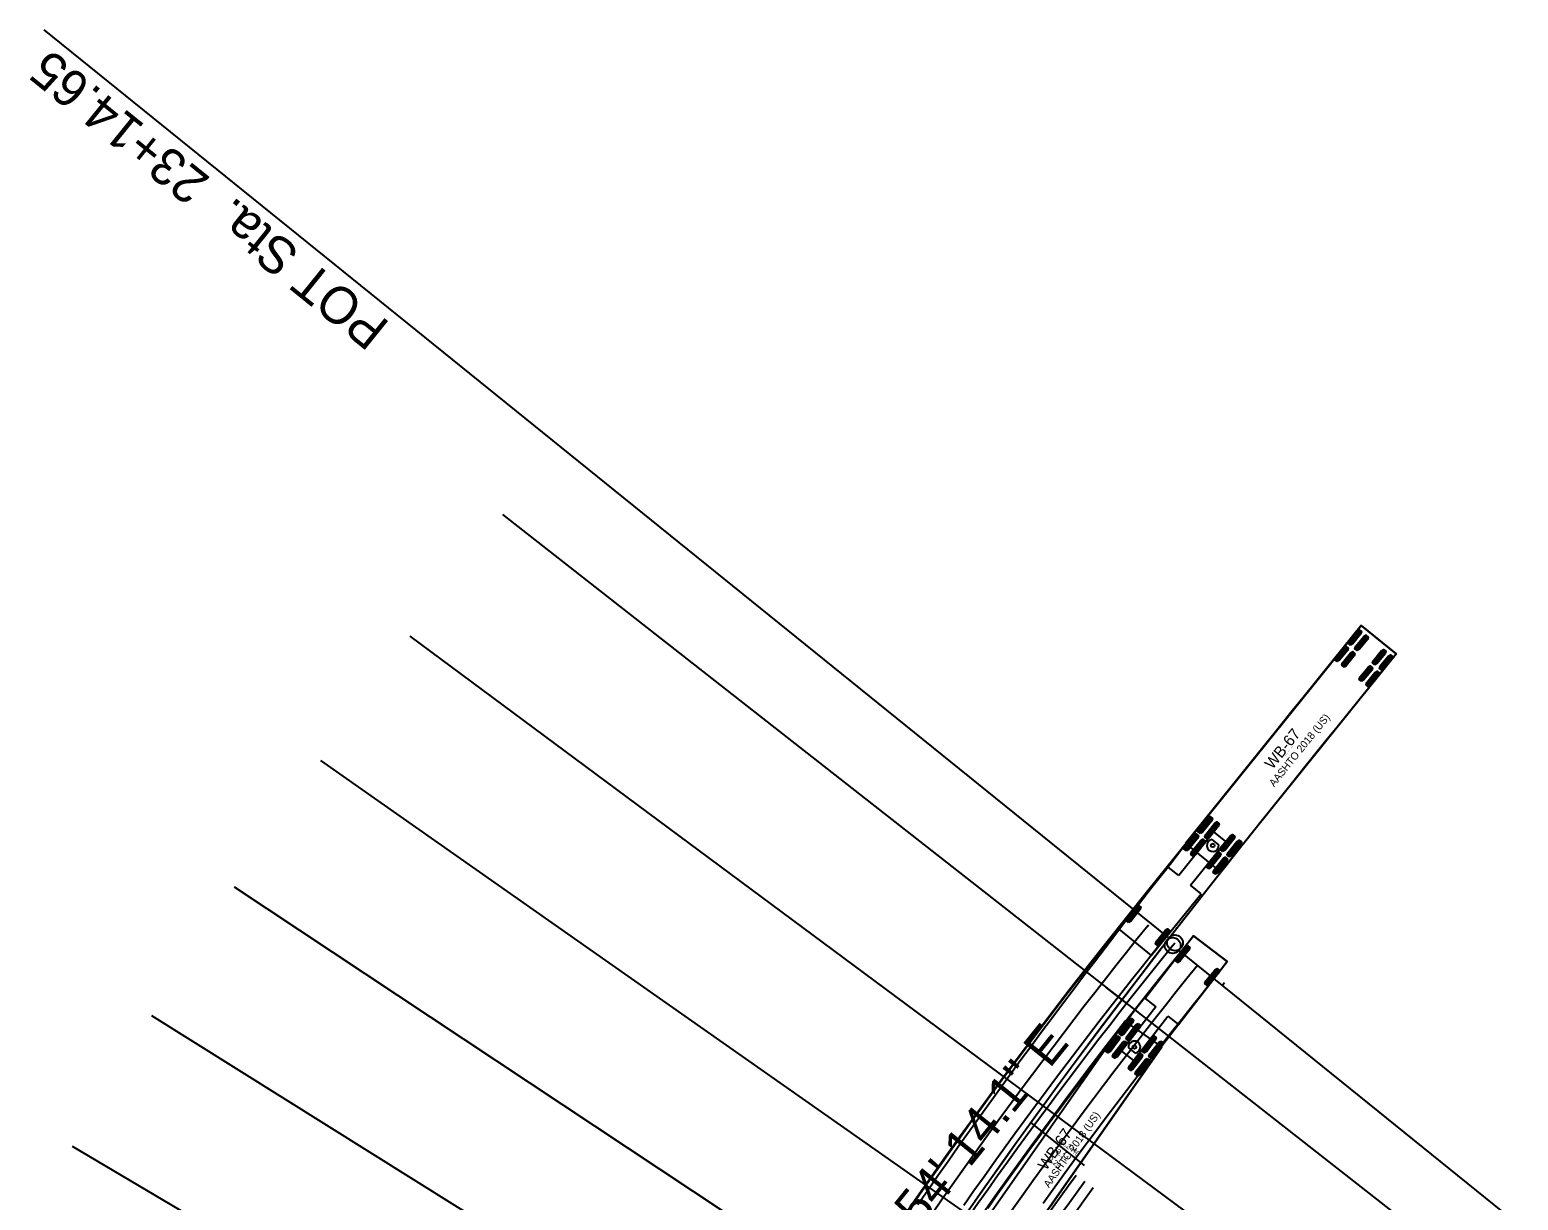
# Model space of a CAD drawing. Extents: x 2293233 to 2294507, y 892788 to 894229.
# Drawn here: x 2294076 to 2294357.6, y 894007.4 to 894228.8 of the extents above; entities that cross this region are included whole.
import ezdxf

# ---------------------------------------------------------------- set-up
doc = ezdxf.new("R2010")
doc.units = 0
for name, color, linetype in [('COGO Default Curve', 7, 'Continuous'), ('Default', 7, 'Continuous'), ('Prop EOT', 7, 'Continuous'), ('Prop Horizontal Alignment', 7, 'Continuous'), ('Prop Paved Shoulder', 7, 'Continuous'), ('Scratch_Level_4', 7, 'Continuous'), ('Scratch_Level_5', 7, 'Continuous'), ('Scratch_Level_6', 7, 'Continuous')]:
    doc.layers.add(name, color=color, linetype=linetype)

msp = doc.modelspace()

# ---------------------------------------------------------------- linework, layer by layer
at = {"layer": 'COGO Default Curve'}
for p, q in [((2294327.95, 894116.1), (2294294.66, 894074.86)), ((2294334.56, 894110.76), (2294327.95, 894116.1)), ((2294325.52, 894112.73), (2294327.59, 894115.3)), ((2294325.7, 894112.58), (2294327.77, 894115.15)), ((2294325.87, 894112.44), (2294327.95, 894115.01)), ((2294326.8, 894111.69), (2294328.87, 894114.26)), ((2294326.98, 894111.55), (2294329.05, 894114.11)), ((2294327.16, 894111.4), (2294329.23, 894113.97)), ((2294301.28, 894069.52), (2294334.56, 894110.76)), ((2294323.01, 894109.61), (2294325.08, 894112.18)), ((2294323.18, 894109.47), (2294325.26, 894112.04)), ((2294323.36, 894109.33), (2294325.43, 894111.89)), ((2294324.29, 894108.58), (2294326.36, 894111.15)), ((2294324.47, 894108.43), (2294326.54, 894111)), ((2294324.65, 894108.29), (2294326.72, 894110.86)), ((2294330.13, 894109), (2294332.21, 894111.57)), ((2294330.31, 894108.86), (2294332.39, 894111.42)), ((2294330.49, 894108.71), (2294332.56, 894111.28)), ((2294331.42, 894107.96), (2294333.49, 894110.53)), ((2294331.6, 894107.82), (2294333.67, 894110.39)), ((2294331.78, 894107.68), (2294333.85, 894110.24)), ((2294327.62, 894105.89), (2294329.7, 894108.46)), ((2294327.8, 894105.74), (2294329.87, 894108.31)), ((2294327.98, 894105.6), (2294330.05, 894108.17)), ((2294328.91, 894104.85), (2294330.98, 894107.42)), ((2294329.08, 894104.71), (2294331.16, 894107.28)), ((2294329.26, 894104.56), (2294331.34, 894107.13)), ((2294297.08, 894077.1), (2294299.39, 894079.95)), ((2294297.26, 894076.95), (2294299.57, 894079.81)), ((2294297.44, 894076.81), (2294299.74, 894079.66)), ((2294300.06, 894077.06), (2294293.4, 894068.81)), ((2294294.45, 894073.83), (2294296.75, 894076.68)), ((2294294.63, 894073.68), (2294296.93, 894076.54)), ((2294298.37, 894076.06), (2294300.67, 894078.91)), ((2294298.55, 894075.92), (2294300.85, 894078.77)), ((2294298.73, 894075.77), (2294301.03, 894078.63)), ((2294302.29, 894075.26), (2294300.06, 894077.06)), ((2294301.31, 894073.68), (2294303.62, 894076.54)), ((2294294.66, 894074.86), (2294301.28, 894069.52)), ((2294294.8, 894073.54), (2294297.11, 894076.39)), ((2294295.63, 894067.01), (2294302.29, 894075.26)), ((2294295.73, 894072.79), (2294298.03, 894075.65)), ((2294295.91, 894072.65), (2294298.21, 894075.5)), ((2294296.09, 894072.5), (2294298.39, 894075.36)), ((2294300.99, 894074.64), (2294299.73, 894075.66)), ((2294301.49, 894073.54), (2294303.79, 894076.39)), ((2294301.67, 894073.4), (2294303.97, 894076.25)), ((2294302.6, 894072.65), (2294304.9, 894075.5)), ((2294302.78, 894072.5), (2294305.08, 894075.36)), ((2294302.95, 894072.36), (2294305.26, 894075.21)), ((2294298.68, 894070.42), (2294300.98, 894073.27)), ((2294298.85, 894070.27), (2294301.16, 894073.13)), ((2294299.03, 894070.13), (2294301.33, 894072.98)), ((2294299.96, 894069.38), (2294302.26, 894072.23)), ((2294300.14, 894069.24), (2294302.44, 894072.09)), ((2294300.32, 894069.09), (2294302.62, 894071.95)), ((2294291.4, 894070.42), (2294281.98, 894058.75)), ((2294293.4, 894068.81), (2294291.4, 894070.42)), ((2294301.28, 894069.52), (2294301.28, 894069.52)), ((2294288.21, 894053.72), (2294297.63, 894065.39)), ((2294297.63, 894065.39), (2294295.63, 894067.01)), ((2294283.52, 894060.29), (2294285.82, 894063.14)), ((2294283.7, 894060.14), (2294286, 894063)), ((2294283.88, 894060), (2294286.18, 894062.85)), ((2294281.98, 894058.75), (2294288.21, 894053.72)), ((2294296.23, 894057.42), (2294287.05, 894045.55)), ((2294289.03, 894055.84), (2294291.33, 894058.69)), ((2294289.21, 894055.7), (2294291.51, 894058.55)), ((2294289.39, 894055.55), (2294291.69, 894058.41)), ((2294302.55, 894052.53), (2294296.23, 894057.42)), ((2294296.23, 894057.42), (2294296.23, 894057.42)), ((2294295.12, 894055.55), (2294292.82, 894052.7)), ((2294295.3, 894055.41), (2294293, 894052.56)), ((2294295.48, 894055.27), (2294293.17, 894052.41)), ((2294288.21, 894053.72), (2294288.21, 894053.72)), ((2294293.38, 894040.66), (2294302.55, 894052.53)), ((2294300.71, 894051.21), (2294298.41, 894048.35)), ((2294300.89, 894051.06), (2294298.59, 894048.21)), ((2294301.07, 894050.92), (2294298.77, 894048.07)), ((2294287.05, 894045.55), (2294289.08, 894043.98)), ((2294289.08, 894043.98), (2294282.6, 894035.6)), ((2294283.26, 894041.28), (2294252.82, 893997.89)), ((2294284.44, 894041.8), (2294282.2, 894038.9)), ((2294284.62, 894041.66), (2294282.38, 894038.76)), ((2294284.8, 894041.52), (2294282.56, 894038.62)), ((2294290.22, 894036.4), (2294283.26, 894041.28)), ((2294283.26, 894041.28), (2294283.26, 894041.28)), ((2294285.74, 894040.79), (2294283.5, 894037.89)), ((2294285.93, 894040.65), (2294283.68, 894037.75)), ((2294286.11, 894040.51), (2294283.86, 894037.61)), ((2294284.87, 894033.85), (2294291.35, 894042.23)), ((2294291.35, 894042.23), (2294293.38, 894040.66)), ((2294281.87, 894038.48), (2294279.63, 894035.58)), ((2294282.05, 894038.34), (2294279.81, 894035.44)), ((2294282.23, 894038.2), (2294279.99, 894035.3)), ((2294283.18, 894037.47), (2294280.93, 894034.57)), ((2294283.36, 894037.33), (2294281.11, 894034.43)), ((2294283.54, 894037.19), (2294281.3, 894034.29)), ((2294288.74, 894038.48), (2294286.49, 894035.58)), ((2294288.92, 894038.34), (2294286.68, 894035.44)), ((2294289.1, 894038.2), (2294286.86, 894035.3)), ((2294290.04, 894037.47), (2294287.8, 894034.57)), ((2294290.22, 894037.33), (2294287.98, 894034.43)), ((2294290.41, 894037.19), (2294288.16, 894034.29)), ((2294259.78, 893993.01), (2294290.22, 894036.4)), ((2294282.6, 894035.6), (2294284.87, 894033.85)), ((2294283.88, 894036.24), (2294285.16, 894035.25)), ((2294286.17, 894035.16), (2294283.93, 894032.25)), ((2294286.35, 894035.02), (2294284.11, 894032.11)), ((2294286.53, 894034.88), (2294284.29, 894031.97)), ((2294287.47, 894034.15), (2294285.23, 894031.25)), ((2294287.66, 894034.01), (2294285.41, 894031.11)), ((2294287.84, 894033.87), (2294285.59, 894030.97))]:
    msp.add_line(p, q, dxfattribs=at)
for points in [[(2294240.06, 894002.5), (2294243.86, 894007.98), (2294247.88, 894013.71), (2294251.95, 894019.4), (2294256.06, 894025.07), (2294260.2, 894030.7), (2294264.39, 894036.31), (2294268.62, 894041.89), (2294272.88, 894047.43), (2294279.86, 894056.36), (2294287.54, 894066.01), (2294327.09, 894115.04), (2294327.76, 894115.84), (2294327.95, 894116.1), (2294334.56, 894110.76), (2294333.71, 894109.7)], [(2294325.12, 894112.6), (2294323.03, 894110), (2294320.93, 894107.41), (2294318.84, 894104.82), (2294316.75, 894102.22), (2294314.65, 894099.63), (2294312.56, 894097.03), (2294310.47, 894094.43), (2294308.38, 894091.83), (2294306.29, 894089.23), (2294304.21, 894086.62), (2294302.13, 894084.02), (2294300.05, 894081.41), (2294297.97, 894078.8), (2294295.89, 894076.18), (2294293.82, 894073.56), (2294291.76, 894070.94), (2294289.7, 894068.31), (2294287.64, 894065.68), (2294285.59, 894063.05), (2294283.54, 894060.41), (2294281.5, 894057.76), (2294279.47, 894055.11), (2294277.44, 894052.46), (2294275.41, 894049.8), (2294273.4, 894047.14), (2294271.39, 894044.47), (2294269.39, 894041.79), (2294267.39, 894039.11), (2294265.4, 894036.43), (2294263.42, 894033.74), (2294261.45, 894031.04), (2294259.48, 894028.34), (2294257.52, 894025.63), (2294255.57, 894022.91), (2294253.63, 894020.19), (2294251.7, 894017.47), (2294249.77, 894014.74), (2294247.85, 894012), (2294245.94, 894009.25), (2294244.04, 894006.5)], [(2294333.71, 894109.7), (2294313.42, 894084.53), (2294306.55, 894075.93), (2294300.54, 894068.36), (2294294.37, 894060.49), (2294288.65, 894053.11), (2294283.18, 894045.97), (2294277.95, 894039.05), (2294272.38, 894031.56), (2294267.06, 894024.3), (2294261.79, 894017), (2294256.78, 894009.93), (2294251.82, 894002.81)], [(2294331.73, 894107.26), (2294329.64, 894104.67), (2294327.55, 894102.07), (2294325.46, 894099.48), (2294323.36, 894096.89), (2294321.27, 894094.29), (2294319.18, 894091.7), (2294317.1, 894089.1), (2294315.01, 894086.51), (2294312.93, 894083.91), (2294310.85, 894081.31), (2294308.77, 894078.71), (2294306.69, 894076.11), (2294304.62, 894073.51), (2294302.56, 894070.9), (2294300.5, 894068.3), (2294298.44, 894065.68), (2294296.39, 894063.07), (2294294.34, 894060.45), (2294292.3, 894057.83), (2294290.26, 894055.21), (2294288.23, 894052.58), (2294286.21, 894049.94), (2294284.19, 894047.3), (2294282.18, 894044.66), (2294280.18, 894042.02), (2294278.18, 894039.36), (2294276.2, 894036.71), (2294274.21, 894034.04), (2294272.24, 894031.38), (2294270.27, 894028.71), (2294268.31, 894026.03), (2294266.36, 894023.35), (2294264.42, 894020.66), (2294262.48, 894017.96), (2294260.55, 894015.26), (2294258.64, 894012.56), (2294256.72, 894009.85), (2294254.82, 894007.13)], [(2294284.49, 894061.86), (2294282.4, 894059.26), (2294280.32, 894056.65), (2294278.24, 894054.03), (2294276.18, 894051.41), (2294274.12, 894048.77), (2294272.07, 894046.13), (2294270.03, 894043.48), (2294268, 894040.83), (2294265.98, 894038.16), (2294263.96, 894035.49), (2294261.96, 894032.81), (2294259.96, 894030.13), (2294257.98, 894027.44), (2294256, 894024.74), (2294254.03, 894022.03), (2294252.08, 894019.32), (2294250.13, 894016.6), (2294248.19, 894013.87), (2294246.26, 894011.13), (2294244.34, 894008.39), (2294242.43, 894005.65)], [(2294290.72, 894056.83), (2294288.63, 894054.24), (2294286.56, 894051.64), (2294284.49, 894049.03), (2294282.43, 894046.42), (2294280.39, 894043.8), (2294278.35, 894041.18), (2294276.32, 894038.54), (2294274.3, 894035.9), (2294272.3, 894033.26), (2294270.3, 894030.61), (2294268.31, 894027.95), (2294266.33, 894025.28), (2294264.36, 894022.61), (2294262.4, 894019.93), (2294260.44, 894017.24), (2294258.5, 894014.55), (2294256.57, 894011.85), (2294254.65, 894009.15), (2294252.73, 894006.43)], [(2294255.43, 894003.62), (2294258.69, 894008.24), (2294262.18, 894013.12), (2294265.51, 894017.71), (2294269.06, 894022.55), (2294272.43, 894027.09), (2294276.04, 894031.88), (2294279.68, 894036.65), (2294283.14, 894041.13), (2294283.42, 894041.34), (2294289.81, 894049.45), (2294296.23, 894057.42), (2294302.55, 894052.53), (2294301.16, 894050.72), (2294293.41, 894040.7), (2294290.12, 894036.5), (2294290.04, 894036.15), (2294259.02, 893991.91)], [(2294257.27, 894005.92), (2294259.2, 894008.66), (2294261.15, 894011.38), (2294263.11, 894014.1), (2294265.07, 894016.81), (2294267.05, 894019.51), (2294269.03, 894022.21), (2294271.03, 894024.9), (2294273.03, 894027.58), (2294275.04, 894030.26), (2294277.06, 894032.93), (2294279.1, 894035.59), (2294281.14, 894038.24), (2294283.19, 894040.89), (2294285.25, 894043.53), (2294287.32, 894046.16), (2294289.4, 894048.78), (2294291.48, 894051.4), (2294293.58, 894054.01), (2294293.79, 894054.27)], [(2294267.73, 894006.82), (2294269.67, 894009.52), (2294271.61, 894012.21), (2294273.57, 894014.89), (2294275.54, 894017.56), (2294277.52, 894020.23), (2294279.51, 894022.89), (2294281.5, 894025.54), (2294283.51, 894028.18), (2294285.52, 894030.82), (2294287.55, 894033.45), (2294289.58, 894036.08), (2294291.62, 894038.7), (2294293.68, 894041.3), (2294295.74, 894043.91), (2294297.81, 894046.5), (2294299.89, 894049.09), (2294300.1, 894049.35)]]:
    msp.add_lwpolyline(points, dxfattribs=at)
for points in [[(2294325.92, 894112.4), (2294325.47, 894112.76), (2294325.63, 894113.23), (2294327.12, 894115.08), (2294327.55, 894115.33), (2294327.99, 894114.97), (2294327.83, 894114.5), (2294326.34, 894112.65)], [(2294327.2, 894111.37), (2294326.76, 894111.73), (2294326.91, 894112.19), (2294328.41, 894114.04), (2294328.83, 894114.29), (2294329.27, 894113.94), (2294329.12, 894113.47), (2294327.63, 894111.62)], [(2294323.41, 894109.29), (2294322.96, 894109.65), (2294323.12, 894110.12), (2294324.61, 894111.97), (2294325.03, 894112.22), (2294325.48, 894111.86), (2294325.32, 894111.39), (2294323.83, 894109.54)], [(2294324.69, 894108.25), (2294324.25, 894108.61), (2294324.4, 894109.08), (2294325.89, 894110.93), (2294326.32, 894111.18), (2294326.76, 894110.82), (2294326.61, 894110.35), (2294325.11, 894108.51)], [(2294330.54, 894108.68), (2294330.09, 894109.04), (2294330.25, 894109.5), (2294331.74, 894111.35), (2294332.16, 894111.6), (2294332.61, 894111.25), (2294332.45, 894110.78), (2294330.96, 894108.93)], [(2294331.82, 894107.64), (2294331.37, 894108), (2294331.53, 894108.47), (2294333.02, 894110.32), (2294333.45, 894110.57), (2294333.89, 894110.21), (2294333.74, 894109.74), (2294332.24, 894107.89)], [(2294328.02, 894105.56), (2294327.58, 894105.92), (2294327.73, 894106.39), (2294329.23, 894108.24), (2294329.65, 894108.49), (2294330.1, 894108.13), (2294329.94, 894107.66), (2294328.45, 894105.82)], [(2294329.31, 894104.53), (2294328.86, 894104.89), (2294329.02, 894105.36), (2294330.51, 894107.2), (2294330.93, 894107.46), (2294331.38, 894107.1), (2294331.22, 894106.63), (2294329.73, 894104.78)], [(2294297.49, 894076.77), (2294297.04, 894077.13), (2294297.23, 894077.64), (2294298.89, 894079.69), (2294299.34, 894079.99), (2294299.79, 894079.63), (2294299.6, 894079.12), (2294297.94, 894077.06)], [(2294294.85, 894073.51), (2294294.4, 894073.86), (2294294.59, 894074.37), (2294296.25, 894076.43), (2294296.71, 894076.72), (2294297.15, 894076.36), (2294296.96, 894075.85), (2294295.3, 894073.8)], [(2294298.77, 894075.74), (2294298.32, 894076.1), (2294298.51, 894076.6), (2294300.17, 894078.66), (2294300.63, 894078.95), (2294301.07, 894078.59), (2294300.88, 894078.08), (2294299.23, 894076.03)], [(2294301.71, 894073.36), (2294301.27, 894073.72), (2294301.46, 894074.23), (2294303.12, 894076.28), (2294303.57, 894076.57), (2294304.02, 894076.21), (2294303.83, 894075.71), (2294302.17, 894073.65)], [(2294296.13, 894072.47), (2294295.69, 894072.83), (2294295.88, 894073.34), (2294297.53, 894075.39), (2294297.99, 894075.68), (2294298.43, 894075.32), (2294298.25, 894074.81), (2294296.59, 894072.76)], [(2294303, 894072.33), (2294302.55, 894072.68), (2294302.74, 894073.19), (2294304.4, 894075.25), (2294304.86, 894075.54), (2294305.3, 894075.18), (2294305.11, 894074.67), (2294303.45, 894072.62)], [(2294299.08, 894070.09), (2294298.63, 894070.45), (2294298.82, 894070.96), (2294300.48, 894073.01), (2294300.93, 894073.31), (2294301.38, 894072.95), (2294301.19, 894072.44), (2294299.53, 894070.38)], [(2294300.36, 894069.06), (2294299.92, 894069.42), (2294300.1, 894069.92), (2294301.76, 894071.98), (2294302.22, 894072.27), (2294302.66, 894071.91), (2294302.47, 894071.4), (2294300.82, 894069.35)], [(2294283.92, 894059.96), (2294283.48, 894060.32), (2294283.66, 894060.83), (2294285.32, 894062.89), (2294285.78, 894063.18), (2294286.22, 894062.82), (2294286.03, 894062.31), (2294284.38, 894060.26)], [(2294289.43, 894055.52), (2294288.99, 894055.88), (2294289.18, 894056.38), (2294290.83, 894058.44), (2294291.29, 894058.73), (2294291.74, 894058.37), (2294291.55, 894057.86), (2294289.89, 894055.81)], [(2294295.08, 894055.59), (2294295.52, 894055.23), (2294295.33, 894054.72), (2294293.68, 894052.67), (2294293.22, 894052.38), (2294292.77, 894052.74), (2294292.96, 894053.24), (2294294.62, 894055.3)], [(2294300.67, 894051.24), (2294301.11, 894050.88), (2294300.93, 894050.38), (2294299.27, 894048.32), (2294298.81, 894048.03), (2294298.37, 894048.39), (2294298.55, 894048.9), (2294300.21, 894050.95)], [(2294284.39, 894041.84), (2294284.85, 894041.49), (2294284.67, 894040.98), (2294283.05, 894038.89), (2294282.6, 894038.59), (2294282.15, 894038.94), (2294282.33, 894039.45), (2294283.94, 894041.54)], [(2294285.7, 894040.83), (2294286.15, 894040.48), (2294285.97, 894039.97), (2294284.36, 894037.88), (2294283.91, 894037.58), (2294283.46, 894037.93), (2294283.63, 894038.44), (2294285.25, 894040.53)], [(2294281.83, 894038.51), (2294282.28, 894038.16), (2294282.1, 894037.65), (2294280.49, 894035.56), (2294280.03, 894035.26), (2294279.58, 894035.61), (2294279.76, 894036.12), (2294281.37, 894038.21)], [(2294283.13, 894037.5), (2294283.58, 894037.15), (2294283.41, 894036.64), (2294281.79, 894034.55), (2294281.34, 894034.25), (2294280.89, 894034.6), (2294281.07, 894035.12), (2294282.68, 894037.2)], [(2294288.69, 894038.51), (2294289.15, 894038.16), (2294288.97, 894037.65), (2294287.35, 894035.56), (2294286.9, 894035.26), (2294286.45, 894035.61), (2294286.63, 894036.12), (2294288.24, 894038.21)], [(2294290, 894037.5), (2294290.45, 894037.15), (2294290.27, 894036.64), (2294288.66, 894034.55), (2294288.21, 894034.25), (2294287.76, 894034.6), (2294287.93, 894035.11), (2294289.55, 894037.2)], [(2294286.12, 894035.19), (2294286.58, 894034.84), (2294286.4, 894034.33), (2294284.78, 894032.24), (2294284.33, 894031.94), (2294283.88, 894032.29), (2294284.06, 894032.8), (2294285.67, 894034.89)], [(2294287.43, 894034.18), (2294287.88, 894033.83), (2294287.7, 894033.32), (2294286.09, 894031.23), (2294285.64, 894030.93), (2294285.19, 894031.28), (2294285.36, 894031.79), (2294286.98, 894033.88)]]:
    msp.add_lwpolyline(points, close=True, dxfattribs=at)
for centre, radius in [((2294325.12, 894112.6), 0.0417), ((2294331.73, 894107.26), 0.0417), ((2294299.85, 894074.52), 0.34), ((2294284.49, 894061.86), 0.0417), ((2294287.61, 894059.35), 0.0417), ((2294290.72, 894056.83), 0.0417), ((2294293.79, 894054.27), 0.0417), ((2294300.1, 894049.35), 0.0417), ((2294285.02, 894036.38), 0.34)]:
    msp.add_circle(centre, radius, dxfattribs=at)
for centre, radius, start, end in [((2294299.85, 894074.52), 1.14, 96.0961, 6.0961), ((2295031.56, 893458.96), 956, 141.09608, 153.52096), ((2295031.56, 893458.96), 944, 141.09608, 153.52096), ((2294285.02, 894036.38), 1.14, 277.2898, 187.2898)]:
    msp.add_arc(centre, radius, start, end, dxfattribs=at)
at = {"layer": 'Default'}
msp.add_line((2294265.32, 894022.18), (2294275.52, 894013.95), dxfattribs=at)
at = {"layer": 'Prop EOT'}
msp.add_line((2294301.61, 894048.04), (2294302.04, 894048.57), dxfattribs=at)
msp.add_line((2294301.61, 894048.04), (2294302.04, 894048.57), dxfattribs=at)
msp.add_arc((2295031.56, 893458.96), 938, 143.86429, 153.52096, dxfattribs=at)
at = {"layer": 'Prop Horizontal Alignment'}
for p, q in [((2294291.53, 894057.05), (2294078.69, 894228.81)), ((2294292.27, 894055.58), (2294292.7, 894056.1)), ((2294292.27, 894055.58), (2294292.7, 894056.1)), ((2294293.44, 894054.64), (2294506.28, 893882.87)), ((2294283.58, 894044.64), (2294279.64, 894047.72))]:
    msp.add_line(p, q, dxfattribs=at)
for centre in [(2294292.27, 894055.58), (2294292.7, 894056.1)]:
    msp.add_circle(centre, 1.5, dxfattribs=at)
msp.add_arc((2295031.56, 893458.96), 950, 141.09608, 153.52096, dxfattribs=at)
msp.add_arc((2295031.56, 893458.96), 950, 141.09608, 153.52096, dxfattribs=at)
at = {"layer": 'Prop Paved Shoulder'}
msp.add_arc((2295031.56, 893458.96), 936, 143.86429, 153.52096, dxfattribs=at)
at = {"layer": 'Scratch_Level_4'}
for p, q in [((2294165.47, 894137.11), (2294401.68, 893952.16)), ((2294147.93, 894114.09), (2294388.92, 893935.42)), ((2294131, 894090.61), (2294376.61, 893918.34)), ((2294114.69, 894066.69), (2294364.75, 893900.95)), ((2294099.01, 894042.36), (2294353.35, 893883.25)), ((2294083.99, 894017.62), (2294342.42, 893865.26))]:
    msp.add_line(p, q, dxfattribs=at)
at = {"layer": 'Scratch_Level_5'}
msp.add_arc((2295031.56, 893458.96), 934, 143.86429, 153.52096, dxfattribs=at)
at = {"layer": 'Scratch_Level_6'}
msp.add_line((2294265.32, 894022.18), (2294275.52, 894013.95), dxfattribs=at)

# ---------------------------------------------------------------- texts
at = {"layer": 'COGO Default Curve'}
for s, height, rotation, p in [('AASHTO 2018 (US)', 1.4167, 51.0961, (2294311.46, 894085.51)), ('WB-67', 2.125, 51.0961, (2294311.14, 894088.78)), ('(c) 2022 Transoft Solutions, Inc. All rights reserved.', 0.085, 51.0961, (2294313.55, 894091.43)), ('AASHTO 2018 (US)', 1.4167, 54.9443, (2294268.86, 894009.65)), ('WB-67', 2.125, 54.9443, (2294268.33, 894012.9)), ('(c) 2022 Transoft Solutions, Inc. All rights reserved.', 0.085, 54.9443, (2294270.55, 894015.7))]:
    msp.add_text(s, height=height, rotation=rotation, dxfattribs=at).set_placement(p)
at = {"layer": 'Default'}
for s, p in [('13.11', (2294269.48, 894016.9)), ('-2.24%', (2294270.74, 894018.45)), ('-0.29', (2294268.22, 894015.34))]:
    msp.add_text(s, height=1, rotation=321.0961, dxfattribs=at).set_placement(p)
at = {"layer": 'Prop Horizontal Alignment'}
for s, rotation, p in [('POT Sta.  23+14.65', 141.0961, (2294144.38, 894173.23)), ('N 38%%d 54\' 14.1" E', 51.0961, (2294228.11, 893981.55))]:
    msp.add_text(s, height=7, rotation=rotation, dxfattribs=at).set_placement(p)

doc.saveas('drawing.dxf')
